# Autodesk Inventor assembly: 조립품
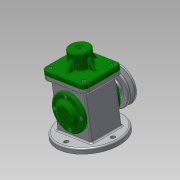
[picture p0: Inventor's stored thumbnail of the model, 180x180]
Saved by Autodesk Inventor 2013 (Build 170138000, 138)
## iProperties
Created: 2018-10
Part Number: 조립품
Document SubType Name: Assembly
Designer: Administrator
Author: Administrator
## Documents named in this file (18)
- C:\Users\Administrator\Desktop\481007V1055\조립품.iam
- C:\Users\Administrator\Desktop\481007V1055\E-링.ipt
- C:\Users\Administrator\Desktop\481007V1055\V-벨트풀리.ipt
- C:\Users\Administrator\Desktop\481007V1055\덮개.ipt
- C:\Users\Administrator\Desktop\481007V1055\뒤커버.ipt
- C:\Users\Administrator\Desktop\481007V1055\링크.ipt
- C:\Users\Administrator\Desktop\481007V1055\베어링 17 x 40 x 12.ipt
- C:\Users\Administrator\Desktop\481007V1055\본체.ipt
- C:\Users\Administrator\Desktop\481007V1055\볼트 M4 x 8.ipt
- C:\Users\Administrator\Desktop\481007V1055\볼트 M4 x 10.ipt
- C:\Users\Administrator\Desktop\481007V1055\슬라이더.ipt
- C:\Users\Administrator\Desktop\481007V1055\앞커버.ipt
- C:\Users\Administrator\Desktop\481007V1055\오일 실 17 30 8.ipt
- C:\Users\Administrator\Desktop\481007V1055\와셔 4x16.ipt
- C:\Users\Administrator\Desktop\481007V1055\클레비스 핀 6 x 22.ipt
- 클레비스 핀 6 x 22.ipt
- C:\Users\Administrator\Desktop\481007V1055\키 4 x 4 x 12.ipt
- C:\Users\Administrator\Desktop\481007V1055\편심축.ipt
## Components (2 placed, 2 different names)
1. E-링:1
2. V-벨트풀리:1
